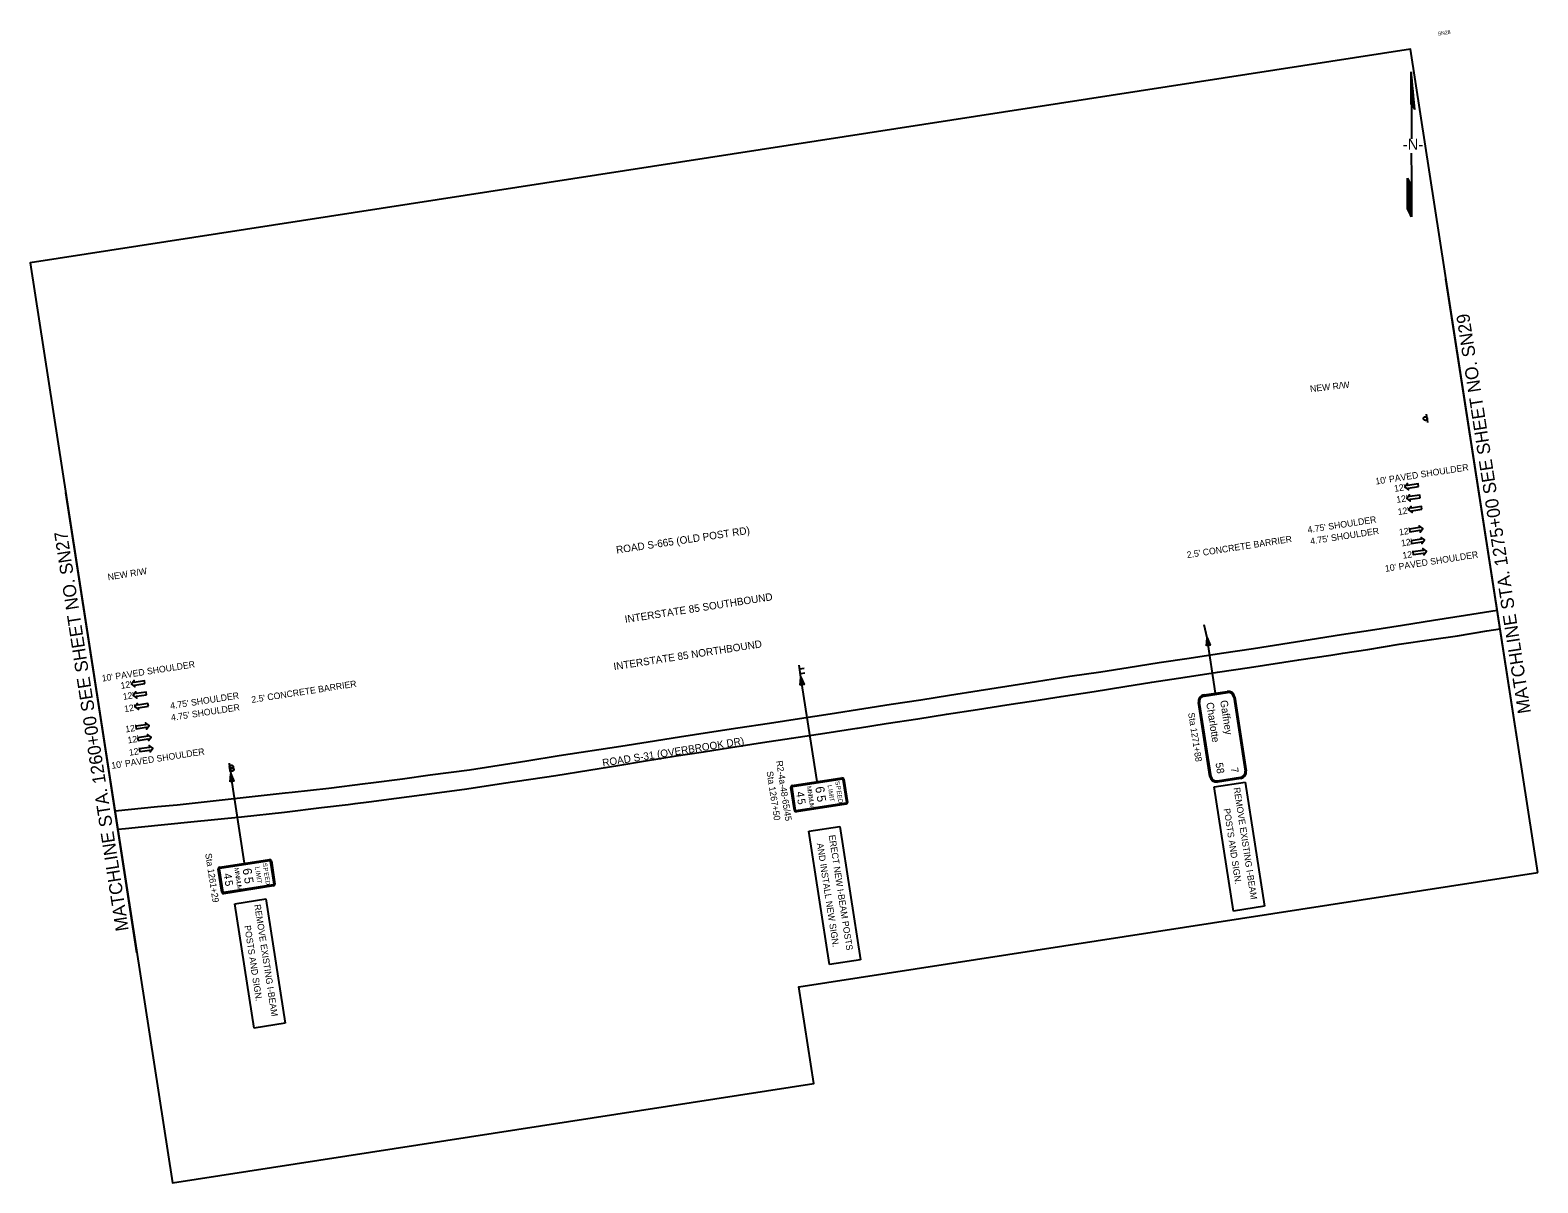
# Model space of a CAD drawing. Extents: x 1775287 to 1776906, y 1179390 to 1180628.
import ezdxf

# ---------------------------------------------------------------- set-up
doc = ezdxf.new("R2010")
doc.units = 0
for name, color, linetype in [('RD_DTM_BkLn1', 7, 'Continuous'), ('RD_DTM_BkLn2', 7, 'Continuous'), ('RD_EX_Conc', 7, 'Continuous'), ('RD_EX_DR_Inlet_txCode', 7, 'Continuous'), ('RD_EX_Driveway', 7, 'Continuous'), ('RD_EX_Fence_ChLk', 7, 'Continuous'), ('RD_EX_H2O', 7, 'Continuous'), ('RD_EX_Road', 7, 'Continuous'), ('RD_EX_SU_Elec', 7, 'Continuous'), ('RD_SMD_Locator', 7, 'Continuous')]:
    doc.layers.add(name, color=color, linetype=linetype)

# ---------------------------------------------------------------- blocks, each defined once
blk = doc.blocks.new('NA5')
at = {"layer": 'RD_DTM_BkLn1'}
for p, q in [((47.5, 65.9), (26.8, 37.4)), ((26.8, 30.6), (47.5, 65.9)), ((27.2, 37.5), (14.5, 19.8)), ((28.1, 38.3), (26.8, 30.6)), ((14.5, 19.8), (5.5, 7.2)), ((-3.5, -5.3), (-18.5, -26.3)), ((-18.5, -26.3), (-43.3, -60.9)), ((-30.6, -36.2), (-22.3, -24.7)), ((-22.3, -24.7), (-24, -34)), ((-41.6, -51.6), (-30.6, -36.2)), ((-43.3, -60.9), (-41.6, -51.6))]:
    blk.add_line(p, q, dxfattribs=at)
for points in [[(27.4, 37.8), (47.4, 65.8)], [(27.6, 37.9), (46.9, 64.9)], [(27.1, 37.6), (39.2, 54.5)], [(27.5, 34.9), (37.5, 48.8)], [(27.6, 35.5), (39, 51.5)], [(27.6, 35.3), (38.5, 50.6)], [(27.6, 35.1), (38, 49.7)], [(27.7, 36.2), (40.6, 54.2)], [(27.7, 36), (40.1, 53.3)], [(27.7, 35.8), (39.6, 52.4)], [(27.8, 38.1), (46.4, 64)], [(27.8, 36.8), (42.2, 56.8)], [(27.8, 36.6), (41.7, 56)], [(27.8, 36.4), (41.1, 55.1)], [(27.9, 37.4), (43.8, 59.5)], [(27.9, 37.2), (43.2, 58.6)], [(27.9, 37), (42.7, 57.7)], [(28, 38.1), (45.3, 62.2)], [(28, 37.9), (44.8, 61.3)], [(28, 37.7), (44.3, 60.4)], [(28.1, 38.3), (45.8, 63.1)], [(26.9, 37.5), (29.9, 41.7)], [(26.9, 31.3), (28.5, 33.6)], [(26.9, 31.1), (28, 32.7)], [(27, 32), (30.1, 36.3)], [(27, 31.8), (29.6, 35.4)], [(27, 31.5), (29.1, 34.5)], [(27.1, 32.6), (31.7, 39)], [(27.1, 32.4), (31.2, 38.1)], [(27.1, 32.2), (30.6, 37.2)], [(27.2, 33.2), (33.3, 41.6)], [(27.2, 33), (32.7, 40.7)], [(27.2, 32.8), (32.2, 39.9)], [(27.3, 33.9), (34.8, 44.3)], [(27.3, 33.7), (34.3, 43.4)], [(27.3, 33.4), (33.8, 42.5)], [(27.4, 34.5), (36.4, 47)], [(27.4, 34.3), (35.9, 46.1)], [(27.4, 34.1), (35.4, 45.2)], [(27.5, 34.7), (36.9, 47.9)], [(26.8, 30.7), (27, 30.9)], [(26.9, 30.9), (27.5, 31.8)], [(-43, -59), (-23.7, -32.1)], [(-43, -59.2), (-23.7, -32.3)], [(-42.9, -58.6), (-23.6, -31.7)], [(-42.9, -58.8), (-23.7, -31.9)], [(-42.8, -58.1), (-23.5, -31.2)], [(-42.8, -58.3), (-23.6, -31.4)], [(-42.7, -57.5), (-23.4, -30.6)], [(-42.7, -57.7), (-23.5, -30.8)], [(-42.7, -57.9), (-23.5, -31)], [(-42.6, -57), (-23.3, -30.1)], [(-42.6, -57.2), (-23.4, -30.4)], [(-42.5, -56.4), (-23.2, -29.5)], [(-42.5, -56.6), (-23.2, -29.7)], [(-42.5, -56.8), (-23.3, -29.9)], [(-42.4, -55.9), (-23.1, -29)], [(-42.4, -56.1), (-23.2, -29.3)], [(-42.3, -55.3), (-23, -28.4)], [(-42.3, -55.5), (-23, -28.6)], [(-42.3, -55.7), (-23.1, -28.8)], [(-42.2, -54.8), (-22.9, -27.9)], [(-42.2, -55), (-23, -28.2)], [(-42.1, -54.4), (-22.8, -27.5)], [(-42.1, -54.6), (-22.9, -27.7)], [(-42, -53.7), (-22.7, -26.8)], [(-42, -53.9), (-22.7, -27.1)], [(-42, -54.2), (-22.8, -27.3)], [(-41.9, -53.3), (-22.6, -26.4)], [(-41.9, -53.5), (-22.7, -26.6)], [(-41.8, -52.6), (-22.5, -25.7)], [(-41.8, -52.8), (-22.5, -26)], [(-41.8, -53.1), (-22.6, -26.2)], [(-41.7, -52.2), (-22.4, -25.3)], [(-41.7, -52.4), (-22.5, -25.5)], [(-41.6, -51.7), (-22.3, -24.9)], [(-41.6, -52), (-22.4, -25.1)], [(-43.3, -60.8), (-24, -33.9)], [(-43.2, -60.1), (-23.9, -33.2)], [(-43.2, -60.3), (-23.9, -33.4)], [(-43.2, -60.5), (-24, -33.6)], [(-43.1, -59.7), (-23.8, -32.8)], [(-43.1, -59.9), (-23.9, -33)], [(-43, -59.4), (-23.8, -32.5)]]:
    blk.add_lwpolyline(points, dxfattribs=at)
blk.add_text('-N-', height=11.81, rotation=324.3865, dxfattribs=at).set_placement((-8.8, 3))
blk = doc.blocks.new('SARRW2')
at = {"layer": 'RD_EX_Driveway'}
blk.add_lwpolyline([(-12, 1.2), (-12, -1.2), (-2.8, -1.2), (-2.8, -2.8), (0, 0), (-2.8, 2.8), (-2.8, 1.2)], close=True, dxfattribs=at)

msp = doc.modelspace()

# ---------------------------------------------------------------- linework, layer by layer
at = {"layer": 'RD_DTM_BkLn2'}
for points in [[(1776883.7, 1179866.6), (1776845.5, 1180113.6), (1776807.2, 1180360.7)], [(1775401.4, 1179637.1), (1775363.2, 1179884.1), (1775324.9, 1180131.2)]]:
    msp.add_lwpolyline(points, dxfattribs=at)
at = {"layer": 'RD_EX_DR_Inlet_txCode'}
msp.add_lwpolyline([(1776905.9, 1179723.3), (1776769, 1180607.7), (1775286.7, 1180378.2), (1775439.6, 1179390), (1776128.5, 1179496.7), (1776112.4, 1179600.4)], close=True, dxfattribs=at)
at = {"layer": 'RD_EX_Fence_ChLk'}
for p, q in [((1776787.7, 1180206.7), (1776786.5, 1180215.6)), ((1776550.7, 1179975.3), (1776547.6, 1179989.5)), ((1776559.8, 1179915.9), (1776550.7, 1179975.3)), ((1776114.5, 1179933.1), (1776112.5, 1179946)), ((1776113.1, 1179942), (1776118.1, 1179942.7)), ((1776113.9, 1179937), (1776118.8, 1179937.8)), ((1776131.9, 1179821), (1776114.5, 1179933.1)), ((1776579.3, 1179911.7), (1776591.6, 1179832.3)), ((1776580.5, 1179911.8), (1776592.8, 1179832.5)), ((1775500.4, 1179840.9), (1775501.2, 1179831.9)), ((1775500.7, 1179838.1), (1775502.1, 1179829.2)), ((1775516.9, 1179733.2), (1775502.1, 1179829.2)), ((1776107.5, 1179789.9), (1776103.7, 1179814.8)), ((1776105.2, 1179816.8), (1776158.5, 1179825.1)), ((1776160.6, 1179823.6), (1776164.5, 1179798.7)), ((1776558.4, 1179815.4), (1776591.6, 1179820.5)), ((1776579.1, 1179681.9), (1776558.4, 1179815.4)), ((1776591.6, 1179820.5), (1776612.3, 1179687.1)), ((1776163, 1179796.6), (1776109.6, 1179788.4)), ((1776123.1, 1179767.7), (1776156.3, 1179772.8)), ((1776145.3, 1179624.4), (1776123.1, 1179767.7)), ((1776156.3, 1179772.8), (1776178.5, 1179629.5)), ((1775490.2, 1179729.1), (1775543.6, 1179737.3)), ((1775490.2, 1179729.1), (1775543.6, 1179737.3)), ((1775545.7, 1179735.8), (1775549.5, 1179710.9)), ((1775545.7, 1179735.8), (1775549.5, 1179710.9)), ((1775492.6, 1179702.1), (1775488.7, 1179727)), ((1775492.6, 1179702.1), (1775488.7, 1179727)), ((1775548, 1179708.9), (1775494.6, 1179700.6)), ((1775548, 1179708.9), (1775494.6, 1179700.6)), ((1775506.6, 1179689.7), (1775539.9, 1179694.9)), ((1775527.3, 1179556.3), (1775506.6, 1179689.7)), ((1775539.9, 1179694.9), (1775560.5, 1179561.4)), ((1776612.3, 1179687.1), (1776579.1, 1179681.9)), ((1776178.5, 1179629.5), (1776145.3, 1179624.4)), ((1775560.5, 1179561.4), (1775527.3, 1179556.3))]:
    msp.add_line(p, q, dxfattribs=at)
for points in [[(1776549.9, 1179966.9), (1776550.7, 1179975.3), (1776553.9, 1179967.5)], [(1776113.7, 1179924.7), (1776114.5, 1179933.1), (1776117.8, 1179925.3)], [(1775501.3, 1179820.8), (1775502.1, 1179829.2), (1775505.3, 1179821.4)]]:
    msp.add_lwpolyline(points, close=True, dxfattribs=at)
for points in [[(1776547.4, 1179914), (1776572.3, 1179917.9)], [(1776547.6, 1179912.8), (1776572.5, 1179916.7)], [(1776553.7, 1179826.5), (1776541.4, 1179905.8)], [(1776554.9, 1179826.6), (1776542.6, 1179906)], [(1776108, 1179790), (1776104.1, 1179814.9)], [(1776108.7, 1179790.1), (1776104.9, 1179815)], [(1776105.3, 1179816.4), (1776158.6, 1179824.7)], [(1776105.4, 1179815.7), (1776158.7, 1179823.9)], [(1776159.4, 1179823.4), (1776163.3, 1179798.5)], [(1776160.2, 1179823.5), (1776164, 1179798.6)], [(1776586.6, 1179825.5), (1776561.7, 1179821.6)], [(1776586.8, 1179824.3), (1776561.9, 1179820.4)], [(1776162.8, 1179797.8), (1776109.4, 1179789.6)], [(1776162.9, 1179797.1), (1776109.5, 1179788.8)], [(1775490.3, 1179728.6), (1775543.7, 1179736.9)], [(1775490.3, 1179728.6), (1775543.7, 1179736.9)], [(1775490.4, 1179727.9), (1775543.8, 1179736.1)], [(1775490.4, 1179727.9), (1775543.8, 1179736.1)], [(1775544.5, 1179735.6), (1775548.3, 1179710.7)], [(1775544.5, 1179735.6), (1775548.3, 1179710.7)], [(1775545.2, 1179735.8), (1775549.1, 1179710.9)], [(1775545.2, 1179735.8), (1775549.1, 1179710.9)], [(1775493, 1179702.2), (1775489.2, 1179727.1)], [(1775493, 1179702.2), (1775489.2, 1179727.1)], [(1775493.8, 1179702.3), (1775489.9, 1179727.2)], [(1775493.8, 1179702.3), (1775489.9, 1179727.2)], [(1775547.8, 1179710.1), (1775494.5, 1179701.8)], [(1775547.8, 1179710.1), (1775494.5, 1179701.8)], [(1775547.9, 1179709.3), (1775494.6, 1179701.1)], [(1775547.9, 1179709.3), (1775494.6, 1179701.1)]]:
    msp.add_lwpolyline(points, dxfattribs=at)
for centre in [(1776785.1, 1180210.9), (1775502.8, 1179836.6), (1775503.4, 1179834)]:
    msp.add_circle(centre, 2, dxfattribs=at)
for centre, radius, start, end in [((1776548.5, 1179906.9), 7.2, 98.8, 188.8), ((1776548.5, 1179906.9), 6, 98.8, 188.8), ((1776573.4, 1179910.7), 7.2, 8.8, 98.8), ((1776573.4, 1179910.7), 6, 8.8, 98.8), ((1776585.7, 1179831.4), 6, 278.8, 8.8), ((1776585.7, 1179831.4), 7.2, 278.8, 8.8), ((1776105.5, 1179815.1), 1.8, 98.8, 188.8), ((1776105.5, 1179815.1), 1.35, 98.8, 188.8), ((1776105.5, 1179815.1), 0.6, 98.8, 188.8), ((1776158.8, 1179823.3), 1.8, 8.8, 98.8), ((1776158.8, 1179823.3), 1.35, 8.8, 98.8), ((1776158.8, 1179823.3), 0.6, 8.8, 98.8), ((1776560.8, 1179827.6), 7.2, 188.8, 278.8), ((1776560.8, 1179827.6), 6, 188.8, 278.8), ((1776162.7, 1179798.4), 0.6, 278.8, 8.8), ((1776162.7, 1179798.4), 1.35, 278.8, 8.8), ((1776162.7, 1179798.4), 1.8, 278.8, 8.8), ((1776109.3, 1179790.2), 1.8, 188.8, 278.8), ((1776109.3, 1179790.2), 1.35, 188.8, 278.8), ((1776109.3, 1179790.2), 0.6, 188.8, 278.8), ((1775543.9, 1179735.6), 1.8, 8.8, 98.8), ((1775543.9, 1179735.6), 1.8, 8.8, 98.8), ((1775543.9, 1179735.6), 1.35, 8.8, 98.8), ((1775543.9, 1179735.6), 1.35, 8.8, 98.8), ((1775543.9, 1179735.6), 0.6, 8.8, 98.8), ((1775543.9, 1179735.6), 0.6, 8.8, 98.8), ((1775490.5, 1179727.3), 1.8, 98.8, 188.8), ((1775490.5, 1179727.3), 1.8, 98.8, 188.8), ((1775490.5, 1179727.3), 1.35, 98.8, 188.8), ((1775490.5, 1179727.3), 1.35, 98.8, 188.8), ((1775490.5, 1179727.3), 0.6, 98.8, 188.8), ((1775490.5, 1179727.3), 0.6, 98.8, 188.8), ((1775494.4, 1179702.4), 1.8, 188.8, 278.8), ((1775494.4, 1179702.4), 1.8, 188.8, 278.8), ((1775494.4, 1179702.4), 1.35, 188.8, 278.8), ((1775494.4, 1179702.4), 1.35, 188.8, 278.8), ((1775494.4, 1179702.4), 0.6, 188.8, 278.8), ((1775494.4, 1179702.4), 0.6, 188.8, 278.8), ((1775547.7, 1179710.6), 0.6, 278.8, 8.8), ((1775547.7, 1179710.6), 0.6, 278.8, 8.8), ((1775547.7, 1179710.6), 1.35, 278.8, 8.8), ((1775547.7, 1179710.6), 1.35, 278.8, 8.8), ((1775547.7, 1179710.6), 1.8, 278.8, 8.8), ((1775547.7, 1179710.6), 1.8, 278.8, 8.8)]:
    msp.add_arc(centre, radius, start, end, dxfattribs=at)
at = {"layer": 'RD_SMD_Locator'}
for points in [[(1776862.4, 1180004.6), (1776828.3, 1179999.3), (1776793.9, 1179993.9), (1776760.5, 1179988.7), (1776726.2, 1179983.3), (1776695.2, 1179978.5), (1776661.3, 1179973.1), (1776600.5, 1179963.5), (1776566, 1179958.4), (1776531.4, 1179953.2), (1776499.2, 1179948.4), (1776466.1, 1179943.2), (1776436.5, 1179938.6), (1776403.2, 1179933.7), (1776367.6, 1179928.1), (1776335.5, 1179923), (1776305.8, 1179918.6), (1776274.2, 1179913.5), (1776243.4, 1179908.4), (1776211.5, 1179903.7), (1776182.1, 1179899), (1776145.8, 1179893.4), (1776113.1, 1179888.5), (1776080.8, 1179883.4), (1776046.6, 1179878.3), (1776016.2, 1179873.7), (1775984, 1179868.8), (1775950.3, 1179863.3), (1775921.1, 1179858.6), (1775854.9, 1179848.5), (1775820.2, 1179842.9), (1775758.4, 1179833.4), (1775716.4, 1179827.8), (1775686.5, 1179823.6), (1775652.6, 1179819.2), (1775646.6, 1179818.5), (1775607.3, 1179813.7), (1775568, 1179809.3), (1775560.6, 1179808.5), (1775515.4, 1179803.5), (1775479.9, 1179799.5), (1775444.4, 1179795.8), (1775423.5, 1179793.9), (1775377.9, 1179789.1)], [(1775380.8, 1179769.8), (1775389.2, 1179770.7), (1775406.1, 1179772.5), (1775459.1, 1179777.8), (1775513.6, 1179783.3), (1775559.8, 1179788.3), (1775599.6, 1179793), (1775628.1, 1179796.4), (1775635.9, 1179797.4), (1775650.4, 1179799.2), (1775680.2, 1179803.1), (1775721, 1179808.6), (1775755.6, 1179813.3), (1775795.1, 1179819.2), (1775851.2, 1179827.7), (1775886.6, 1179833.2), (1775920, 1179838.6), (1775945.3, 1179842.8), (1775980.5, 1179848.5), (1776009.8, 1179853.1), (1776038.8, 1179857.6), (1776073.2, 1179862.8), (1776104.4, 1179867.7), (1776140.2, 1179872.9), (1776174.6, 1179878.4), (1776175.1, 1179878.5), (1776205.9, 1179883.2), (1776240.2, 1179888.5), (1776270.7, 1179893.4), (1776304.2, 1179898.5), (1776335.7, 1179903.3), (1776347.4, 1179905.1), (1776364.7, 1179907.8), (1776393.8, 1179912.4), (1776429.5, 1179917.9), (1776462.4, 1179923), (1776491.4, 1179927.6), (1776527, 1179933.2), (1776562, 1179938.5), (1776596.2, 1179943.5), (1776649.3, 1179951.6), (1776649.4, 1179951.7), (1776683.7, 1179956.9), (1776696.5, 1179958.9), (1776723.2, 1179963), (1776757.1, 1179968.5), (1776791.6, 1179973.6), (1776819.8, 1179977.6), (1776851.3, 1179983), (1776865.4, 1179985.2)]]:
    msp.add_lwpolyline(points, dxfattribs=at)

# ---------------------------------------------------------------- block references
at = {"layer": 'RD_DTM_BkLn2', "rotation": 35.61349782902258}
msp.add_blockref('NA5', (1776769.8, 1180502.2), dxfattribs=at)
at = {"layer": 'RD_EX_Driveway', "xscale": 1.2}
for p, yscale, rotation in [((1776763.2, 1180137.2), 1.2, -171.19998882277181), ((1776765.1, 1180125.1), 1.2, -171.19998882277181), ((1776767, 1180112.7), 1.2, -171.19998882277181), ((1776782.4, 1180092.8), 1.1999999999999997, 8.800011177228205), ((1776784.3, 1180080.5), 1.1999999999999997, 8.800011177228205), ((1776786.2, 1180068.4), 1.1999999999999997, 8.800011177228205), ((1775395.4, 1179925.6), 1.2, -171.19998882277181), ((1775397.3, 1179913.5), 1.2, -171.19998882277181), ((1775399.2, 1179901.1), 1.2, -171.19998882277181), ((1775414.5, 1179881.2), 1.1999999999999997, 8.800011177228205), ((1775416.5, 1179868.8), 1.1999999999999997, 8.800011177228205), ((1775418.3, 1179856.8), 1.1999999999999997, 8.800011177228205)]:
    msp.add_blockref('SARRW2', p, dxfattribs=dict(at, yscale=yscale, rotation=rotation))

# ---------------------------------------------------------------- texts
at = {"layer": 'RD_DTM_BkLn2'}
for s, p in [('MATCHLINE STA. 1275+00 SEE SHEET NO. SN29', (1776898.5, 1179895.1)), ('MATCHLINE STA. 1260+00 SEE SHEET NO. SN27', (1775392.6, 1179661.4))]:
    msp.add_text(s, height=14, rotation=98.8, dxfattribs=at).set_placement(p)
at = {"layer": 'RD_EX_Conc'}
for rotation, p in [(6.258, (1776661.6, 1180239.3)), (9.2261, (1775370.5, 1180037.1))]:
    msp.add_text('NEW R/W', height=7, rotation=rotation, dxfattribs=at).set_placement(p)
at = {"layer": 'RD_EX_Fence_ChLk'}
for s, height, rotation, p in [('Sta 1271+88', 7, 278.8001, (1776530.3, 1179894.6)), ('Charlotte', 8, 278.8, (1776549.7, 1179905.5)), ('Gaffney', 8, 278.8, (1776564.7, 1179907.8)), ('Sta 1267+50', 7, 278.8001, (1776077.5, 1179831.6)), ('R2-4a-48-65/45', 7, 278.8001, (1776087.8, 1179843)), ('58', 8, 278.8, (1776559.7, 1179840.8)), ('7', 8, 278.8, (1776575.9, 1179835.7)), ('M', 4.8, 278.8, (1776120.8, 1179815.8)), ('6', 9.6, 278.8, (1776129.8, 1179815)), ('L', 4.8, 278.8, (1776143.1, 1179817)), ('I', 4.8, 278.8, (1776143.8, 1179812.6)), ('S', 4.8, 278.8, (1776151.3, 1179821.1)), ('P', 4.8, 278.8, (1776152.1, 1179816.1)), ('REMOVE EXISTING I-BEAM', 7, 278.8001, (1776579.1, 1179814.2)), ('4', 8.4, 278.8, (1776109.3, 1179809.7)), ('5', 8.4, 278.8, (1776110.5, 1179802)), ('I', 4.8, 278.8, (1776121.5, 1179811.7)), ('N', 4.8, 278.8, (1776121.7, 1179810.1)), ('I', 4.8, 278.8, (1776122.3, 1179806.5)), ('M', 4.8, 278.8, (1776122.5, 1179804.8)), ('U', 4.8, 278.8, (1776123.2, 1179800.7)), ('M', 4.8, 278.8, (1776123.7, 1179797.2)), ('5', 9.6, 278.8, (1776131.2, 1179805.5)), ('M', 4.8, 278.8, (1776144.1, 1179810.5)), ('I', 4.8, 278.8, (1776145, 1179804.9)), ('T', 4.8, 278.8, (1776145.2, 1179803.1)), ('E', 4.8, 278.8, (1776152.8, 1179811)), ('E', 4.8, 278.8, (1776153.5, 1179806.5)), ('D', 4.8, 278.8, (1776154.2, 1179802)), ('POSTS AND SIGN.', 7, 278.8001, (1776568.4, 1179791.6)), ('AND INSTALL NEW SIGN.', 7, 278.8001, (1776131.5, 1179754.4)), ('ERECT NEW I-BEAM POSTS', 7, 278.8001, (1776144.3, 1179763.2)), ('Sta 1261+29', 7, 278.8001, (1775474.6, 1179743.4)), ('S', 4.8, 278.8, (1775536.3, 1179733.3)), ('4', 8.4, 278.8, (1775494.4, 1179721.9)), ('M', 4.8, 278.8, (1775505.9, 1179728.1)), ('I', 4.8, 278.8, (1775506.5, 1179724)), ('N', 4.8, 278.8, (1775506.8, 1179722.3)), ('I', 4.8, 278.8, (1775507.3, 1179718.7)), ('M', 4.8, 278.8, (1775507.6, 1179717.1)), ('6', 9.6, 278.8, (1775514.8, 1179727.2)), ('5', 9.6, 278.8, (1775516.3, 1179717.7)), ('L', 4.8, 278.8, (1775528.2, 1179729.3)), ('I', 4.8, 278.8, (1775528.8, 1179724.8)), ('M', 4.8, 278.8, (1775529.2, 1179722.8)), ('I', 4.8, 278.8, (1775530, 1179717.2)), ('T', 4.8, 278.8, (1775530.3, 1179715.4)), ('P', 4.8, 278.8, (1775537.1, 1179728.3)), ('E', 4.8, 278.8, (1775537.9, 1179723.2)), ('E', 4.8, 278.8, (1775538.6, 1179718.8)), ('5', 8.4, 278.8, (1775495.6, 1179714.3)), ('U', 4.8, 278.8, (1775508.2, 1179713)), ('M', 4.8, 278.8, (1775508.8, 1179709.4)), ('D', 4.8, 278.8, (1775539.3, 1179714.3)), ('REMOVE EXISTING I-BEAM', 7, 278.8001, (1775527.3, 1179688.6)), ('POSTS AND SIGN.', 7, 278.8001, (1775516.6, 1179666))]:
    msp.add_text(s, height=height, rotation=rotation, dxfattribs=at).set_placement(p)
at = {"layer": 'RD_EX_H2O'}
for s, p in [("10' PAVED SHOULDER", (1776732, 1180139.9)), ("12'", (1776752.1, 1180132.1)), ("12'", (1776754.5, 1180120.3)), ("4.75' SHOULDER", (1776659.1, 1180087.9)), ("12'", (1776756, 1180107.2)), ("4.75' SHOULDER", (1776662, 1180075.6)), ("12'", (1776757.3, 1180085.3)), ("2.5' CONCRETE BARRIER", (1776529.4, 1180060.9)), ("12'", (1776759.6, 1180073.5)), ("10' PAVED SHOULDER", (1776742.3, 1180046.2)), ("12'", (1776761.1, 1180060.3)), ("10' PAVED SHOULDER", (1775364.1, 1179928.3)), ("12'", (1775384.3, 1179920.5)), ("2.5' CONCRETE BARRIER", (1775524.8, 1179905.4)), ("12'", (1775386.7, 1179908.7)), ("4.75' SHOULDER", (1775437.6, 1179898.8)), ("12'", (1775388.2, 1179895.5)), ("4.75' SHOULDER", (1775438.5, 1179886.2)), ("12'", (1775389.4, 1179873.7)), ("12'", (1775391.8, 1179861.9)), ("10' PAVED SHOULDER", (1775374.4, 1179834.6)), ("12'", (1775393.3, 1179848.7))]:
    msp.add_text(s, height=7, rotation=8.8, dxfattribs=at).set_placement(p)
at = {"layer": 'RD_EX_Road'}
msp.add_text('SN28', height=4, rotation=8.8, dxfattribs=at).set_placement((1776798.7, 1180622.1))
at = {"layer": 'RD_EX_SU_Elec'}
for s, rotation, p in [('ROAD S-665 (OLD POST RD)', 8.4657, (1775916.6, 1180065.8)), ('INTERSTATE 85 SOUTHBOUND', 8.8, (1775925.9, 1179991.3)), ('INTERSTATE 85 NORTHBOUND', 8.8, (1775913.8, 1179940.6)), ('ROAD S-31 (OVERBROOK DR)', 8.9115, (1775901.8, 1179837.1))]:
    msp.add_text(s, height=8, rotation=rotation, dxfattribs=at).set_placement(p)

doc.saveas('drawing.dxf')
